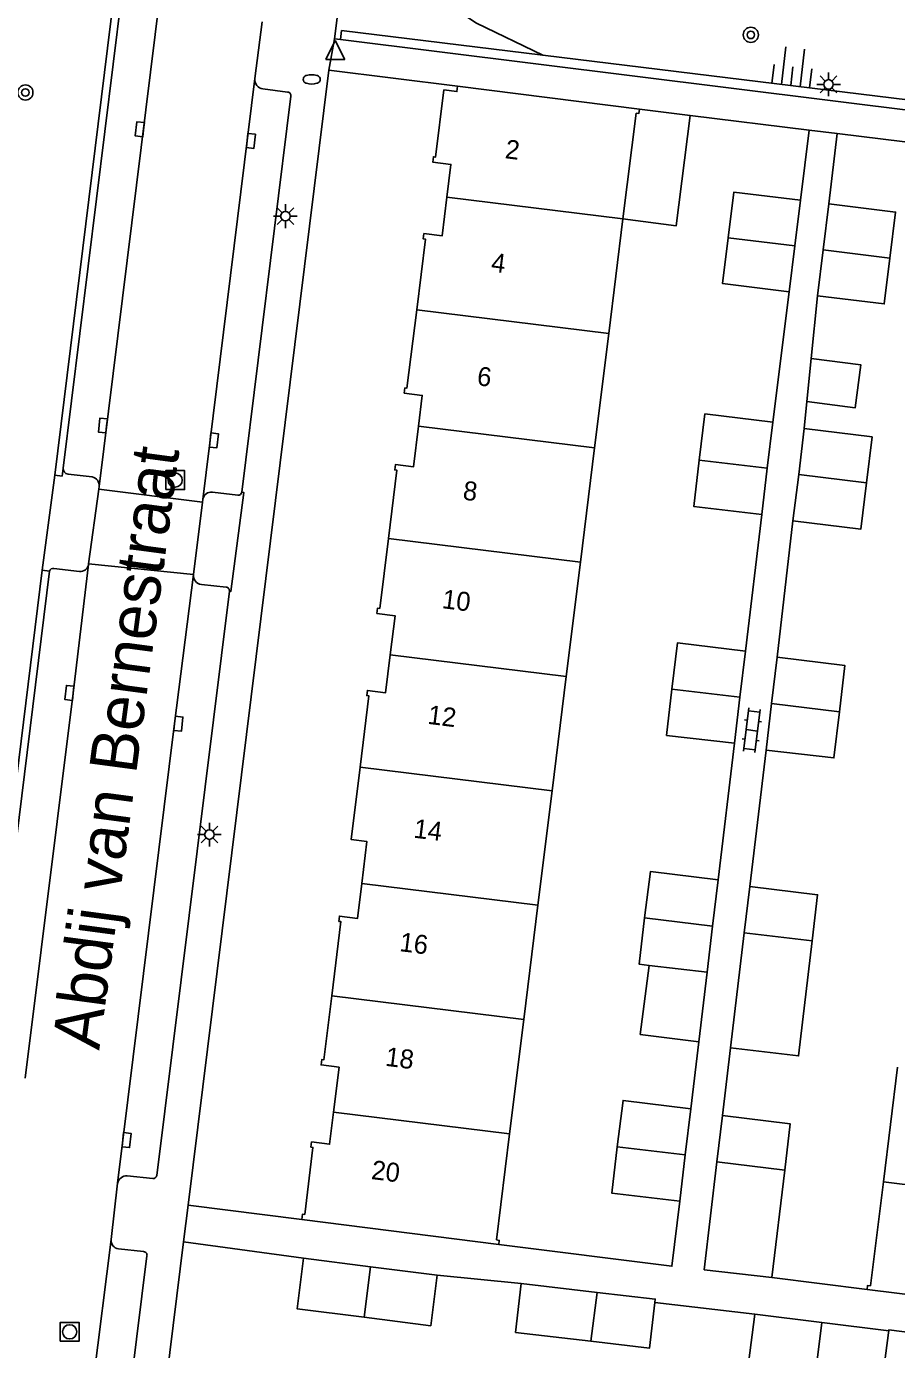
# Model space of a CAD drawing. Extents: x 131000 to 133014, y 396499 to 399001.
# Drawn here: x 131752.2 to 131798.1, y 397226.6 to 397296.4 of the extents above; entities that cross this region are included whole.
import ezdxf

# ---------------------------------------------------------------- set-up
doc = ezdxf.new("R2010")
doc.units = 0
for name, color, linetype in [('gg-afsc-erfafscheiding', 7, 'Continuous'), ('gg-afsc-muur', 7, 'Continuous'), ('gg-anno-huisnummerreeks BGT', 7, 'Continuous'), ('gg-anno-openbare ruimte label', 7, 'Continuous'), ('gg-bbg-bijgebouw', 7, 'Continuous'), ('gg-bbg-gedigitaliseerde bebouwing', 7, 'Continuous'), ('gg-bbg-gedigitaliseerde bijgebouw', 7, 'Continuous'), ('gg-bbg-hoofdgebouw', 7, 'Continuous'), ('gg-bbg-luifel en loopbrug', 7, 'Continuous'), ('gg-bbg-tussenscheiding', 7, 'Continuous'), ('gg-knt-bovenkant onderkant talud', 7, 'Continuous'), ('gg-knt-verharding', 7, 'Continuous'), ('gg-knt-verharding nz', 7, 'Continuous'), ('gt-grn-groengrens', 7, 'Continuous'), ('gt-grn-weggrens', 7, 'Continuous'), ('gt-symb-boom', 7, 'Continuous'), ('gt-symb-brandkraan', 7, 'Continuous'), ('gt-symb-klinker verharding', 7, 'Continuous'), ('gt-symb-kolk', 7, 'Continuous'), ('gt-symb-lichtmast', 7, 'Continuous'), ('gt-symb-rioolschacht', 7, 'Continuous'), ('gt-symb-talud symbool', 7, 'Continuous'), ('gt-symb-waterafsluiter', 7, 'Continuous')]:
    doc.layers.add(name, color=color, linetype=linetype)

# ---------------------------------------------------------------- blocks, each defined once
blk = doc.blocks.new('gt0-KL1')
at = {"layer": 'gt-symb-klinker verharding'}
for p, q in [((-1.15, 0.3), (1.15, 0.3)), ((-1, -0.3), (-1, 0.3)), ((-0.5, 0.3), (-0.5, 0.45)), ((0, -0.3), (0, 0.3)), ((0.5, 0.3), (0.5, 0.45)), ((1, -0.3), (1, 0.3)), ((-1.15, -0.3), (1.15, -0.3)), ((-0.5, -0.45), (-0.5, -0.3)), ((0.5, -0.45), (0.5, -0.3))]:
    blk.add_line(p, q, dxfattribs=at)
blk = doc.blocks.new('gt0-TALUD_1')
at = {"layer": 'gt-symb-talud symbool'}
for p, q in [((0, -1), (0, 0)), ((-1, -1), (-1, 0)), ((-0.5, -2), (-0.5, 0)), ((0.5, -2), (0.5, 0)), ((1, -1), (1, 0))]:
    blk.add_line(p, q, dxfattribs=at)
blk = doc.blocks.new('gt0-LMAST')
at = {"layer": 'gt-symb-lichtmast'}
for p, q in [((-0.182, 0.173), (-0.447, 0.438)), ((-0.005, 0.246), (-0.005, 0.621)), ((0.172, 0.173), (0.437, 0.438)), ((-0.255, -0.004), (-0.63, -0.004)), ((-0.182, -0.181), (-0.447, -0.446)), ((-0.005, -0.254), (-0.005, -0.629)), ((0.437, -0.446), (0.172, -0.181)), ((0.245, -0.004), (0.62, -0.004))]:
    blk.add_line(p, q, dxfattribs=at)
blk.add_circle((-0.005, -0.004), 0.25, dxfattribs=at)
blk = doc.blocks.new('gt0-BOOM')
at = {"layer": 'gt-symb-boom'}
for radius in [0.4, 0.2]:
    blk.add_circle((0, 0), radius, dxfattribs=at)
blk = doc.blocks.new('gt0-WAFSL')
at = {"layer": 'gt-symb-waterafsluiter'}
for p, q in [((-0.5, -0.333), (0, 0.667)), ((0, 0.667), (0.5, -0.333)), ((0.5, -0.333), (-0.5, -0.333))]:
    blk.add_line(p, q, dxfattribs=at)
blk = doc.blocks.new('gt0-KOLK')
at = {"layer": 'gt-symb-kolk'}
blk.add_lwpolyline([(0, 0), (0.375, 0), (0.375, 0.4), (-0.375, 0.4), (-0.375, 0), (0, 0)], dxfattribs=at)
blk = doc.blocks.new('gt0-BR')
at = {"layer": 'gt-symb-brandkraan'}
for centre, radius, start, end in [((-0.244, 0), 0.206, 107.56694, 252.43307), ((0.599, -2.664), 3, 106.89205, 107.56694), ((0, -0.691), 0.938, 73.10799, 106.89205), ((-0.599, -2.664), 3, 72.43309, 73.10799), ((0.244, 0), 0.206, 287.56695, 72.43309), ((0.599, 2.664), 3, 252.43307, 253.10797), ((0, 0.691), 0.938, 253.10797, 286.89206), ((-0.599, 2.664), 3, 286.89206, 287.56695)]:
    blk.add_arc(centre, radius, start, end, dxfattribs=at)
blk = doc.blocks.new('gt0-RS')
at = {"layer": 'gt-symb-rioolschacht'}
blk.add_lwpolyline([(-0.5, -0.5), (0.5, -0.5), (0.5, 0.5), (-0.5, 0.5)], close=True, dxfattribs=at)
blk.add_circle((0, 0), 0.375, dxfattribs=at)

msp = doc.modelspace()

# ---------------------------------------------------------------- linework, layer by layer
at = {"layer": 'gg-afsc-erfafscheiding'}
for p, q in [((131792.43, 397282.408), (131791.565, 397275.528)), ((131793.922, 397282.197), (131793.596, 397278.892)), ((131793.371, 397276.612), (131793.23, 397275.188)), ((131790.985, 397270.662), (131790.124, 397263.454)), ((131792.632, 397270.324), (131791.799, 397263.125)), ((131789.543, 397258.589), (131788.683, 397251.382)), ((131791.215, 397258.234), (131790.354, 397251.038)), ((131787.663, 397242.838), (131787.242, 397239.309)), ((131789.339, 397242.517), (131788.914, 397238.951)), ((131766.737, 397233.474), (131760.734, 397234.227)), ((131766.822, 397231.421), (131760.493, 397232.282)), ((131773.869, 397230.534), (131778.303, 397230.095)), ((131796.545, 397229.776), (131791.52, 397230.406)), ((131785.351, 397229.087), (131790.62, 397228.473))]:
    msp.add_line(p, q, dxfattribs=at)
msp.add_lwpolyline([(131777.113, 397232.151), (131786.251, 397231.005), (131786.661, 397234.443)], dxfattribs=at)
at = {"layer": 'gg-afsc-muur'}
for p, q in [((131787.215, 397291.706), (131793.483, 397290.934)), ((131793.483, 397290.934), (131793.021, 397287.238)), ((131794.96, 397290.76), (131794.518, 397287.043)), ((131803.954, 397289.641), (131794.96, 397290.76))]:
    msp.add_line(p, q, dxfattribs=at)
msp.add_lwpolyline([(131800.011, 397227.348), (131797.692, 397227.654), (131797.68, 397227.588)], dxfattribs=at)
at = {"layer": 'gg-bbg-bijgebouw'}
for p, q in [((131793.021, 397287.238), (131792.726, 397284.823)), ((131794.22, 397284.62), (131794.518, 397287.043)), ((131792.726, 397284.823), (131792.43, 397282.408)), ((131793.922, 397282.197), (131794.22, 397284.62)), ((131766.822, 397231.421), (131770.346, 397230.978)), ((131770.346, 397230.978), (131773.869, 397230.534)), ((131790.62, 397228.473), (131794.15, 397228.031)), ((131794.15, 397228.031), (131797.68, 397227.588)), ((131797.352, 397225.082), (131797.669, 397227.482))]:
    msp.add_line(p, q, dxfattribs=at)
at = {"layer": 'gg-bbg-gedigitaliseerde bebouwing'}
for p, q in [((131783.663, 397286.249), (131784.355, 397291.838)), ((131782.915, 397280.215), (131783.663, 397286.249)), ((131782.168, 397274.182), (131782.915, 397280.215)), ((131781.421, 397268.149), (131782.168, 397274.182)), ((131780.674, 397262.115), (131781.421, 397268.149)), ((131779.927, 397256.082), (131780.674, 397262.115)), ((131779.179, 397250.049), (131779.927, 397256.082)), ((131778.432, 397244.015), (131779.179, 397250.049)), ((131777.685, 397237.982), (131778.432, 397244.015)), ((131797.399, 397235.458), (131798.147, 397241.498)), ((131776.992, 397232.388), (131777.685, 397237.982)), ((131796.721, 397229.976), (131797.399, 397235.458))]:
    msp.add_line(p, q, dxfattribs=at)
at = {"layer": 'gg-bbg-gedigitaliseerde bijgebouw'}
for p, q in [((131791.275, 397273.095), (131791.565, 397275.528)), ((131792.941, 397272.768), (131793.23, 397275.188)), ((131791.275, 397273.095), (131790.985, 397270.662)), ((131792.941, 397272.768), (131792.632, 397270.324)), ((131789.834, 397261.022), (131790.124, 397263.454)), ((131791.799, 397263.125), (131791.499, 397260.68)), ((131789.834, 397261.022), (131789.543, 397258.589)), ((131791.215, 397258.234), (131791.499, 397260.68)), ((131788.393, 397248.949), (131788.683, 397251.382)), ((131790.354, 397251.038), (131790.056, 397248.593)), ((131788.393, 397248.949), (131788.102, 397246.516)), ((131789.339, 397242.517), (131790.056, 397248.593)), ((131788.102, 397246.516), (131785.04, 397246.871)), ((131786.952, 397236.876), (131787.242, 397239.309)), ((131788.914, 397238.951), (131788.613, 397236.507)), ((131786.952, 397236.876), (131786.661, 397234.443)), ((131791.52, 397230.406), (131792.196, 397236.079)), ((131782.313, 397229.626), (131778.303, 397230.095)), ((131790.62, 397228.473), (131790.295, 397225.882)), ((131797.669, 397227.482), (131797.68, 397227.588))]:
    msp.add_line(p, q, dxfattribs=at)
for points in [[(131793.021, 397287.238), (131789.515, 397287.667), (131789.219, 397285.252)], [(131794.518, 397287.043), (131798.042, 397286.61), (131797.744, 397284.187)], [(131789.219, 397285.252), (131788.924, 397282.837), (131792.43, 397282.408)], [(131797.744, 397284.187), (131797.446, 397281.764), (131793.922, 397282.197)], [(131791.565, 397275.528), (131787.992, 397275.967), (131787.692, 397273.523)], [(131793.23, 397275.188), (131796.803, 397274.748), (131796.514, 397272.328)], [(131790.985, 397270.662), (131787.409, 397271.076), (131787.692, 397273.523)], [(131792.632, 397270.324), (131796.205, 397269.885), (131796.514, 397272.328)], [(131790.124, 397263.454), (131786.551, 397263.894), (131786.251, 397261.449)], [(131791.799, 397263.125), (131795.372, 397262.685), (131795.082, 397260.253)], [(131789.543, 397258.589), (131785.967, 397259.003), (131786.251, 397261.449)], [(131791.215, 397258.234), (131794.791, 397257.82), (131795.082, 397260.253)], [(131788.683, 397251.382), (131785.11, 397251.821), (131784.81, 397249.377)], [(131790.354, 397251.038), (131793.929, 397250.598), (131793.639, 397248.165)], [(131785.04, 397246.871), (131784.526, 397246.93), (131784.81, 397249.377)], [(131789.339, 397242.517), (131792.929, 397242.102), (131793.639, 397248.165)], [(131787.242, 397239.309), (131783.669, 397239.748), (131783.368, 397237.304)], [(131788.914, 397238.951), (131792.487, 397238.512), (131792.196, 397236.079)], [(131786.661, 397234.443), (131783.085, 397234.857), (131783.368, 397237.304)], [(131791.52, 397230.406), (131787.955, 397230.818), (131788.613, 397236.507)], [(131766.822, 397231.421), (131766.486, 397228.754), (131770.01, 397228.31)], [(131770.01, 397228.31), (131773.533, 397227.867), (131773.869, 397230.534)], [(131778.303, 397230.095), (131778.001, 397227.513), (131781.973, 397227.05)], [(131782.313, 397229.626), (131785.372, 397229.269), (131785.351, 397229.087)], [(131781.973, 397227.05), (131785.071, 397226.688), (131785.351, 397229.087)]]:
    msp.add_lwpolyline(points, dxfattribs=at)
at = {"layer": 'gg-bbg-hoofdgebouw'}
for p, q in [((131774.94, 397293.26), (131784.532, 397292.037)), ((131777.113, 397232.151), (131766.737, 397233.474)), ((131805.534, 397228.647), (131796.545, 397229.776))]:
    msp.add_line(p, q, dxfattribs=at)
for points in [[(131774.375, 397287.391), (131774.59, 397289.128), (131773.637, 397289.249), (131773.672, 397289.528), (131773.781, 397289.514), (131774.22, 397293.059), (131774.906, 397292.972), (131774.94, 397293.26)], [(131784.532, 397292.037), (131784.504, 397291.819), (131784.355, 397291.838)], [(131772.786, 397281.461), (131773.246, 397285.186), (131773.136, 397285.2), (131773.17, 397285.478), (131774.123, 397285.357), (131774.375, 397287.391)], [(131772.882, 397275.324), (131773.082, 397276.941), (131772.13, 397277.063), (131772.164, 397277.34), (131772.275, 397277.326), (131772.786, 397281.461)], [(131771.293, 397269.394), (131771.739, 397272.999), (131771.629, 397273.013), (131771.663, 397273.291), (131772.615, 397273.17), (131772.882, 397275.324)], [(131771.39, 397263.257), (131771.645, 397265.319), (131770.693, 397265.441), (131770.728, 397265.719), (131770.837, 397265.705), (131771.293, 397269.394)], [(131769.799, 397257.327), (131770.265, 397261.089), (131770.156, 397261.103), (131770.19, 397261.382), (131771.143, 397261.26), (131771.39, 397263.257)], [(131769.889, 397251.191), (131770.156, 397253.412), (131769.328, 397253.518), (131769.799, 397257.327)], [(131768.305, 397245.26), (131768.79, 397249.18), (131768.681, 397249.194), (131768.716, 397249.472), (131769.668, 397249.351), (131769.889, 397251.191)], [(131768.403, 397239.123), (131768.697, 397241.501), (131767.746, 397241.622), (131767.781, 397241.9), (131767.888, 397241.886), (131768.305, 397245.26)], [(131766.737, 397233.474), (131766.771, 397233.752), (131766.88, 397233.738), (131767.317, 397237.271), (131767.209, 397237.285), (131767.244, 397237.563), (131768.195, 397237.441), (131768.403, 397239.123)], [(131776.992, 397232.388), (131777.141, 397232.369), (131777.113, 397232.151)], [(131796.545, 397229.776), (131796.572, 397229.994), (131796.721, 397229.976)]]:
    msp.add_lwpolyline(points, dxfattribs=at)
at = {"layer": 'gg-bbg-luifel en loopbrug'}
for p, q in [((131784.532, 397292.037), (131787.215, 397291.706)), ((131793.596, 397278.892), (131793.371, 397276.612)), ((131788.102, 397246.516), (131787.663, 397242.838))]:
    msp.add_line(p, q, dxfattribs=at)
for points in [[(131783.663, 397286.249), (131786.474, 397285.891), (131787.215, 397291.706)], [(131793.596, 397278.892), (131796.206, 397278.559), (131795.917, 397276.288), (131793.371, 397276.612)], [(131787.663, 397242.838), (131784.576, 397243.232), (131785.04, 397246.871)]]:
    msp.add_lwpolyline(points, dxfattribs=at)
at = {"layer": 'gg-bbg-tussenscheiding'}
for p, q in [((131774.375, 397287.391), (131783.663, 397286.249)), ((131792.726, 397284.823), (131789.219, 397285.252)), ((131797.744, 397284.187), (131794.22, 397284.62)), ((131772.786, 397281.461), (131782.915, 397280.215)), ((131772.882, 397275.324), (131782.168, 397274.182)), ((131787.692, 397273.523), (131791.275, 397273.095)), ((131796.514, 397272.328), (131792.941, 397272.768)), ((131771.293, 397269.394), (131781.421, 397268.149)), ((131771.39, 397263.257), (131780.674, 397262.115)), ((131786.251, 397261.449), (131789.834, 397261.022)), ((131791.499, 397260.68), (131795.082, 397260.253)), ((131769.799, 397257.327), (131779.927, 397256.082)), ((131769.889, 397251.191), (131779.179, 397250.049)), ((131784.81, 397249.377), (131788.393, 397248.949)), ((131790.056, 397248.593), (131793.639, 397248.165)), ((131768.305, 397245.26), (131778.432, 397244.015)), ((131768.403, 397239.123), (131777.685, 397237.982)), ((131783.368, 397237.304), (131786.952, 397236.876)), ((131788.613, 397236.507), (131792.196, 397236.079)), ((131805.285, 397234.489), (131797.399, 397235.458)), ((131770.01, 397228.31), (131770.346, 397230.978)), ((131781.973, 397227.05), (131782.313, 397229.626)), ((131793.83, 397225.481), (131794.15, 397228.031))]:
    msp.add_line(p, q, dxfattribs=at)
at = {"layer": 'gg-knt-bovenkant onderkant talud'}
msp.add_line((131779.445, 397294.881), (131805.589, 397291.691), dxfattribs=at)
msp.add_lwpolyline([(131769.282, 397302.332), (131772.2, 397299.054), (131775.947, 397296.57), (131779.445, 397294.881)], dxfattribs=at)
at = {"layer": 'gg-knt-verharding'}
for p, q in [((131753.694, 397272.736), (131758.205, 397309.164)), ((131758.596, 397309.116), (131754.141, 397273.103)), ((131769.282, 397302.332), (131768.457, 397295.758)), ((131764.634, 397296.647), (131764.251, 397293.655)), ((131768.457, 397295.758), (131768.769, 397295.719)), ((131812.647, 397290.238), (131768.769, 397295.719)), ((131768.16, 397294.1), (131760.734, 397234.227)), ((131774.94, 397293.26), (131768.16, 397294.1)), ((131764.681, 397293.108), (131765.978, 397292.944)), ((131766.15, 397292.723), (131763.565, 397271.832)), ((131793.483, 397290.934), (131794.96, 397290.76)), ((131755.667, 397272.64), (131754.398, 397272.791)), ((131756.017, 397272), (131755.481, 397268.049)), ((131756.037, 397272.144), (131756.017, 397272)), ((131761.494, 397271.314), (131756.017, 397272)), ((131763.355, 397271.675), (131762.011, 397271.839)), ((131761.494, 397271.314), (131761.021, 397267.487)), ((131761.512, 397271.456), (131761.494, 397271.314)), ((131750.239, 397241.909), (131753.43, 397267.677)), ((131753.03, 397267.726), (131753.43, 397267.677)), ((131753.655, 397267.809), (131754.996, 397267.651)), ((131755.481, 397268.049), (131755.478, 397268.027)), ((131761.021, 397267.487), (131755.481, 397268.049)), ((131761.431, 397266.964), (131762.734, 397266.828)), ((131762.907, 397266.61), (131759.077, 397235.786)), ((131758.864, 397235.629), (131757.512, 397235.772)), ((131757.016, 397235.39), (131756.665, 397232.415)), ((131760.493, 397232.282), (131758.333, 397214.867)), ((131758.562, 397231.547), (131756.324, 397213.643)), ((131757.059, 397231.915), (131758.386, 397231.774))]:
    msp.add_line(p, q, dxfattribs=at)
for points in [[(131754.141, 397273.103), (131754.089, 397272.687), (131753.694, 397272.736)], [(131762.907, 397266.61), (131762.991, 397266.599), (131763.671, 397271.818), (131763.565, 397271.832)], [(131753.03, 397267.726), (131749.792, 397241.518), (131750.177, 397241.465), (131750.239, 397241.909)]]:
    msp.add_lwpolyline(points, dxfattribs=at)
for centre, radius, start, end in [((131764.744, 397293.6), 0.496, 173.59931, 262.74289), ((131765.976, 397292.765), 0.179, 346.54199, 89.24387), ((131754.436, 397273.084), 0.296, 176.34061, 262.61718), ((131755.579, 397272.188), 0.461, 354.51724, 78.92627), ((131761.957, 397271.393), 0.449, 83.06205, 171.95295), ((131763.376, 397271.866), 0.192, 263.81187, 349.75311), ((131753.61, 397267.628), 0.187, 76.10564, 164.69181), ((131755.039, 397268.093), 0.444, 264.49612, 351.41825), ((131761.485, 397267.429), 0.468, 172.8298, 263.35875), ((131762.724, 397266.643), 0.185, 349.81418, 87.0553), ((131757.493, 397235.284), 0.488, 87.71235, 167.4918), ((131758.89, 397235.817), 0.19, 262.20628, 350.58078), ((131757.131, 397232.377), 0.467, 175.32851, 261.14771), ((131758.379, 397231.587), 0.187, 347.67365, 87.90137)]:
    msp.add_arc(centre, radius, start, end, dxfattribs=at)
at = {"layer": 'gg-knt-verharding nz'}
for p, q in [((131756.037, 397272.144), (131760.68, 397309.509)), ((131764.251, 397293.655), (131761.512, 397271.456)), ((131760.493, 397232.282), (131760.734, 397234.227)), ((131756.665, 397232.415), (131754.288, 397213.286))]:
    msp.add_line(p, q, dxfattribs=at)
for points in [[(131752.145, 397240.928), (131754.668, 397261.226), (131755.478, 397268.027)], [(131761.021, 397267.487), (131760.021, 397259.64), (131757.016, 397235.39)]]:
    msp.add_lwpolyline(points, dxfattribs=at)
at = {"layer": 'gt-grn-groengrens'}
msp.add_line((131753.03, 397267.726), (131753.694, 397272.736), dxfattribs=at)
msp.add_lwpolyline([(131779.445, 397294.881), (131768.827, 397296.183), (131768.769, 397295.719)], dxfattribs=at)
at = {"layer": 'gt-grn-weggrens'}
msp.add_line((131768.16, 397294.1), (131768.457, 397295.758), dxfattribs=at)

# ---------------------------------------------------------------- block references
at = {"layer": 'gt-symb-boom'}
for p in [(131790.41, 397295.962), (131752.151, 397292.92)]:
    msp.add_blockref('gt0-BOOM', p, dxfattribs=at)
at = {"layer": 'gt-symb-brandkraan'}
msp.add_blockref('gt0-BR', (131767.25, 397293.613), dxfattribs=at)
at = {"layer": 'gt-symb-klinker verharding', "rotation": 82.9887502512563}
msp.add_blockref('gt0-KL1', (131790.467, 397259.274), dxfattribs=at)
at = {"layer": 'gt-symb-kolk'}
for p, rotation in [((131758.384, 397290.958), 84.00113167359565), ((131763.842, 397290.387), -95.99886832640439), ((131756.436, 397275.334), 84.00113167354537), ((131761.893, 397274.591), -95.99886832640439), ((131754.668, 397261.226), 84.00113167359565), ((131760.021, 397259.64), -95.99886832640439), ((131757.29, 397237.681), -95.99886832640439)]:
    msp.add_blockref('gt0-KOLK', p, dxfattribs=dict(at, rotation=rotation))
at = {"layer": 'gt-symb-lichtmast'}
for p in [(131794.516, 397293.353), (131765.867, 397286.401), (131761.859, 397253.777)]:
    msp.add_blockref('gt0-LMAST', p, dxfattribs=at)
at = {"layer": 'gt-symb-rioolschacht'}
for p in [(131760.05, 397272.473), (131754.485, 397227.542)]:
    msp.add_blockref('gt0-RS', p, dxfattribs=at)
at = {"layer": 'gt-symb-talud symbool', "xscale": 0.9997524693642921, "yscale": 0.9997524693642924, "rotation": 173.33703637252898}
msp.add_blockref('gt0-TALUD_1', (131792.517, 397293.286), dxfattribs=at)
at = {"layer": 'gt-symb-waterafsluiter'}
msp.add_blockref('gt0-WAFSL', (131768.493, 397295.002), dxfattribs=at)

# ---------------------------------------------------------------- texts
at = {"layer": 'gg-anno-huisnummerreeks BGT'}
for s, p in [('2', (131777.413, 397289.458)), ('4', (131776.674, 397283.48)), ('6', (131775.933, 397277.483)), ('8', (131775.186, 397271.45)), ('10', (131774.086, 397265.722)), ('12', (131773.33, 397259.62)), ('14', (131772.587, 397253.615)), ('16', (131771.845, 397247.63)), ('18', (131771.097, 397241.581)), ('20', (131770.358, 397235.607))]:
    msp.add_text(s, height=1, rotation=352.9, dxfattribs=at).set_placement(p)
at = {"layer": 'gg-anno-openbare ruimte label'}
msp.add_text('Abdij van Bernestraat', height=2.5, rotation=82.4, dxfattribs=at).set_placement((131756.042, 397242.369))

doc.saveas('drawing.dxf')
